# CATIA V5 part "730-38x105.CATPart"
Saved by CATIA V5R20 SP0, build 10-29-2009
Part number: 730-38x105
Definition: NONE
Nomenclature: 730-38x105
Source: Unknown
Description: 730-38x105
Bounding box of the stored display mesh (mm): x -23 to 23, y -22.5 to 22.5, z 0 to 105
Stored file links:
  C:\Users\Utente\Desktop\IO LAVORO\3D X SITO CF\X SITO\730\730-38x105.CATPart
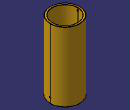
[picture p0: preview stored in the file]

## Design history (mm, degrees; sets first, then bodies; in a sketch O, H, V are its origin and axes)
Body1 "730-38x105" (main body)
  Solid1: solid without history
